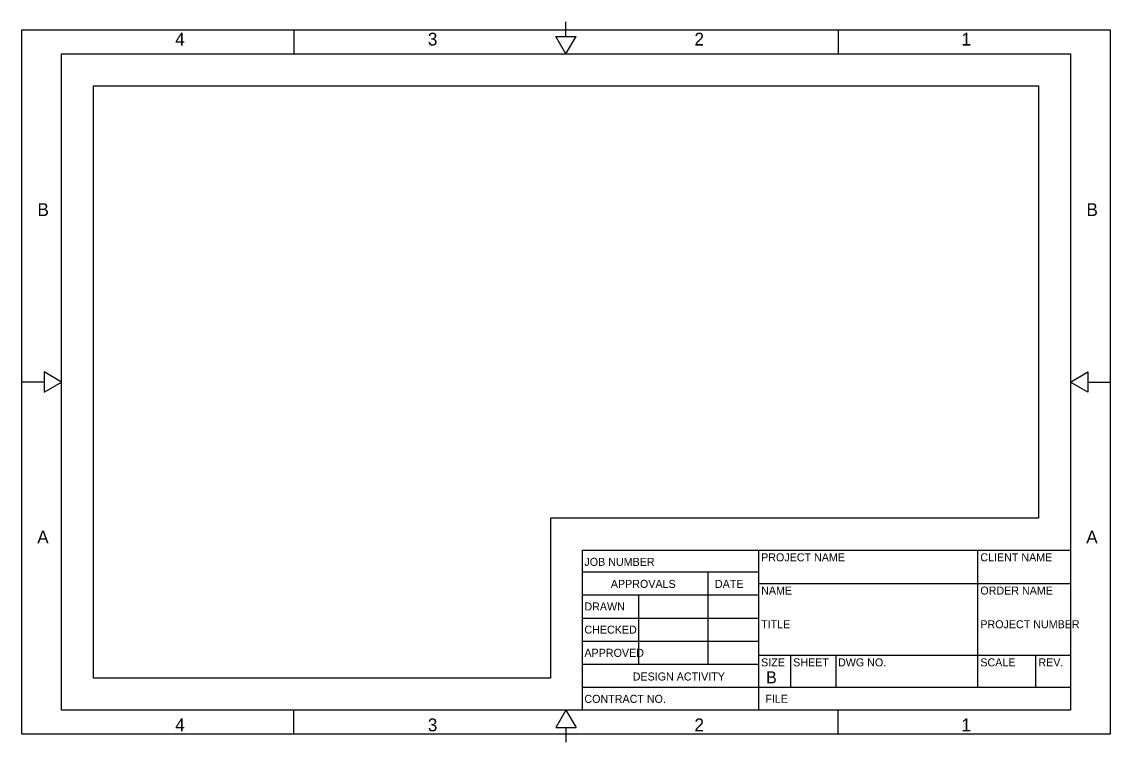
# Model space of a CAD drawing. Extents: x 0 to 1.42, y -0.01 to 0.93.
import ezdxf

# ---------------------------------------------------------------- set-up
doc = ezdxf.new("R2010")
doc.units = 0
for name, color, linetype in [('Border_outline', 7, 'Continuous'), ('BorderPlot', 7, 'Continuous'), ('ClipShape', 7, 'Continuous'), ('TitleBlock', 7, 'Continuous'), ('TitleBlockText', 7, 'Continuous')]:
    doc.layers.add(name, color=color, linetype=linetype)

msp = doc.modelspace()

# ---------------------------------------------------------------- linework, layer by layer
at = {"layer": 'Border_outline'}
for p, q in [((0.7083, 0.908), (0.7083, 0.9271)), ((0.3542, 0.9167), (0.3542, 0.8854)), ((0.7083, 0.8854), (0.6953, 0.908)), ((0.6953, 0.908), (0.7214, 0.908)), ((0.7083, 0.8854), (0.7214, 0.908)), ((1.0625, 0.9167), (1.0625, 0.8854)), ((0.0517, 0.4583), (0.0291, 0.4714)), ((0.0291, 0.4714), (0.0291, 0.4453)), ((1.365, 0.4583), (1.3876, 0.4714)), ((1.3876, 0.4714), (1.3876, 0.4453)), ((0.0291, 0.4583), (0, 0.4583)), ((0.0291, 0.4453), (0.0517, 0.4583)), ((1.3876, 0.4453), (1.365, 0.4583)), ((1.3876, 0.4583), (1.4167, 0.4583)), ((0.3542, 0), (0.3542, 0.0312)), ((0.7083, 0.0312), (0.6953, 0.0086)), ((0.7083, 0.0312), (0.7214, 0.0086)), ((1.0625, 0), (1.0625, 0.0312)), ((0.6953, 0.0086), (0.7214, 0.0086)), ((0.7083, 0.0086), (0.7083, -0.0104))]:
    msp.add_line(p, q, dxfattribs=at)
msp.add_lwpolyline([(1.365, 0.0312), (0.0517, 0.0312), (0.0517, 0.8854), (1.365, 0.8854)], close=True, dxfattribs=at)
at = {"layer": 'BorderPlot'}
msp.add_lwpolyline([(0, 0.9167), (1.4167, 0.9167), (1.4167, 0), (0, 0)], close=True, dxfattribs=at)
at = {"layer": 'ClipShape'}
for p, q in [((0.0933, 0.0729), (0.0933, 0.8437)), ((0.0933, 0.8437), (1.3233, 0.8437)), ((1.3233, 0.8437), (1.3233, 0.2812)), ((1.3233, 0.2812), (0.6883, 0.2812)), ((0.6883, 0.2812), (0.6883, 0.0729)), ((0.6883, 0.0729), (0.0933, 0.0729))]:
    msp.add_line(p, q, dxfattribs=at)
at = {"layer": 'TitleBlock'}
for p, q in [((0.73, 0.0312), (0.73, 0.2396)), ((0.73, 0.2396), (1.365, 0.2396)), ((0.9592, 0.0312), (0.9592, 0.2396)), ((1.2443, 0.0612), (1.2443, 0.2396)), ((0.73, 0.2112), (0.9592, 0.2112)), ((0.8932, 0.0912), (0.8932, 0.2112)), ((0.9592, 0.1962), (1.365, 0.1962)), ((0.73, 0.1812), (0.9592, 0.1812)), ((0.8033, 0.0912), (0.8033, 0.1812)), ((0.73, 0.1512), (0.9592, 0.1512)), ((0.73, 0.1212), (0.9592, 0.1212)), ((0.9592, 0.1029), (1.365, 0.1029)), ((1.0008, 0.0612), (1.0008, 0.1029)), ((1.0601, 0.0612), (1.0601, 0.1029)), ((1.3199, 0.0612), (1.3199, 0.1029)), ((0.73, 0.0912), (0.9592, 0.0912)), ((0.73, 0.0612), (1.365, 0.0612)), ((1.365, 0.0312), (1.365, 0.0312))]:
    msp.add_line(p, q, dxfattribs=at)

# ---------------------------------------------------------------- texts
at = {"layer": 'Border_outline'}
for s, p in [('4', (0.1997, 0.8962)), ('3', (0.5285, 0.8962)), ('3', (0.5285, 0.8962)), ('2', (0.8755, 0.8962)), ('1', (1.2231, 0.8962)), ('B', (0.0204, 0.6743)), ('B', (1.3857, 0.6743)), ('A', (0.0201, 0.2482)), ('A', (1.3854, 0.2482)), ('4', (0.1997, 0.0038)), ('3', (0.5285, 0.0038)), ('2', (0.8755, 0.0038)), ('1', (1.2231, 0.0038))]:
    msp.add_text(s, height=0.0167, dxfattribs=at).set_placement(p)
at = {"layer": 'TitleBlock'}
msp.add_text('B', height=0.0156, dxfattribs=at).set_placement((0.9687, 0.0662))
at = {"layer": 'TitleBlockText'}
for s, height, p in [('JOB NUMBER', 0.01042, (0.7323, 0.2191)), ('PROJECT NAME', 0.010417, (0.9623, 0.225)), ('CLIENT NAME', 0.010417, (1.2476, 0.225)), ('APPROVALS', 0.01042, (0.7667, 0.1904)), ('DATE', 0.01042, (0.9022, 0.1904)), ('NAME', 0.01042, (0.9623, 0.1817)), ('ORDER NAME', 0.01042, (1.2476, 0.1817)), ('DRAWN', 0.01042, (0.7323, 0.161)), ('TITLE', 0.01042, (0.9623, 0.1379)), ('PROJECT NUMBER', 0.010417, (1.2476, 0.1379)), ('CHECKED', 0.01042, (0.7323, 0.1309)), ('APPROVED', 0.01042, (0.7323, 0.1007)), ('SIZE', 0.01042, (0.9623, 0.0883)), ('SHEET', 0.01042, (1.004, 0.0883)), ('DWG NO.', 0.01042, (1.0624, 0.0883)), ('SCALE', 0.01042, (1.2476, 0.0883)), ('REV.', 0.01042, (1.3232, 0.0883)), ('DESIGN ACTIVITY', 0.010417, (0.7952, 0.0699)), ('CONTRACT NO.', 0.010417, (0.7323, 0.0408)), ('FILE', 0.01042, (0.9678, 0.0409))]:
    msp.add_text(s, height=height, dxfattribs=at).set_placement(p)

doc.saveas('drawing.dxf')
